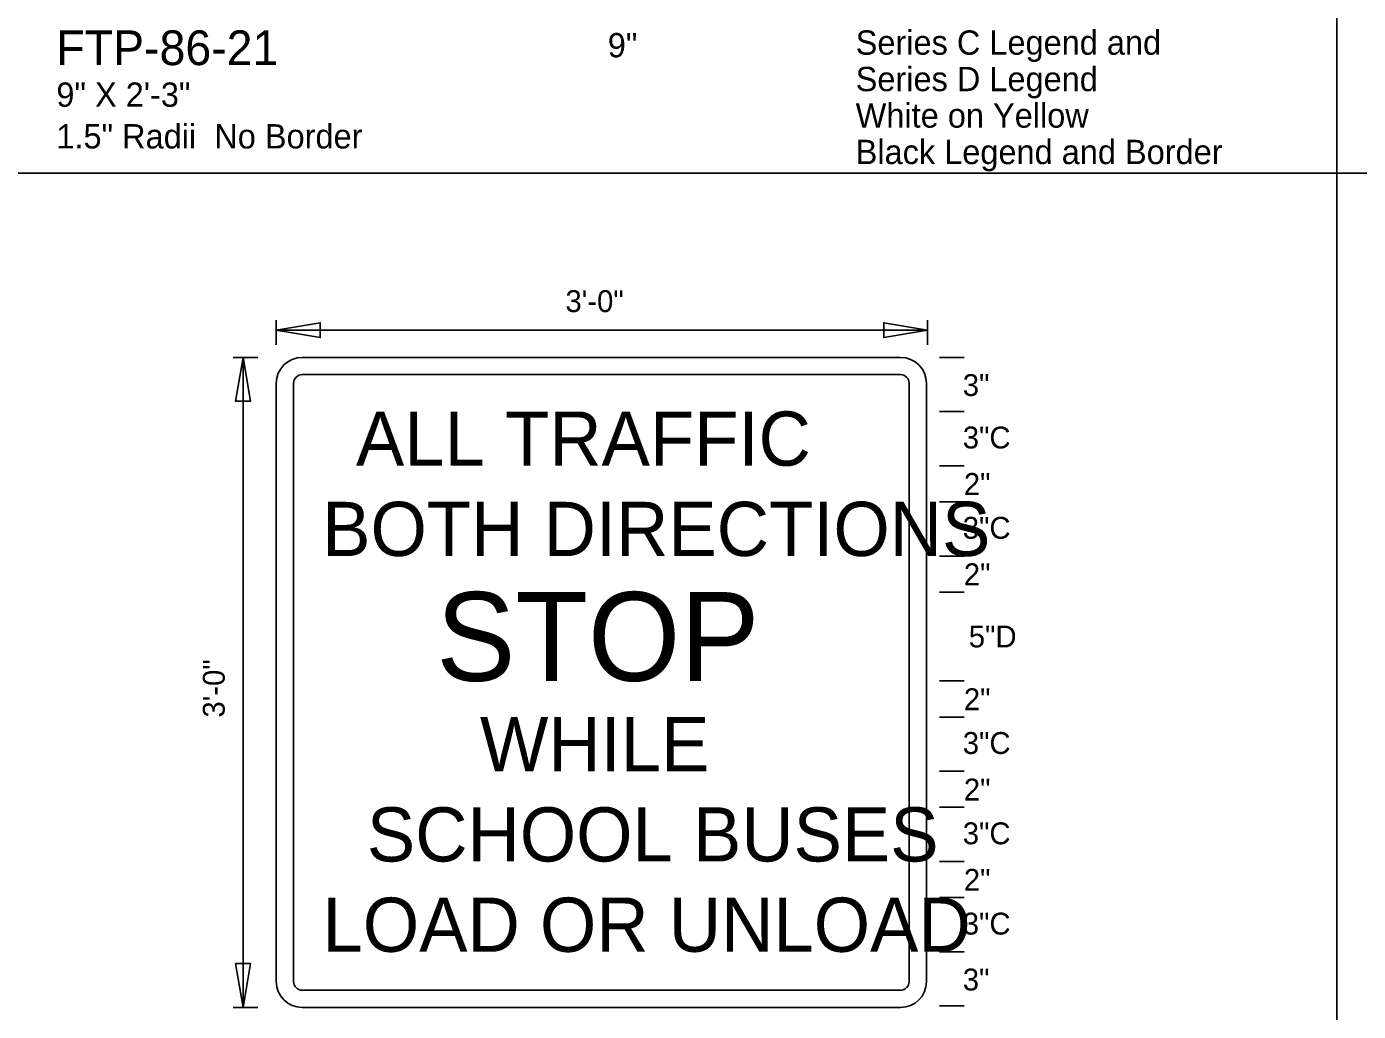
# Model space of a CAD drawing. Extents: x 0 to 770, y 0 to 495.
# Drawn here: x 196.4 to 388.1, y 209.3 to 351.1 of the extents above; entities that cross this region are included whole.
import ezdxf

# ---------------------------------------------------------------- set-up
doc = ezdxf.new("R2010")
doc.units = 0
for name, color, linetype in [('Default', 7, 'Continuous'), ('Dimension', 7, 'Continuous'), ('GSBWFill', 7, 'Continuous'), ('GSDims', 7, 'Continuous'), ('SheetLines_dp', 7, 'Continuous'), ('TextStructures', 7, 'Continuous')]:
    doc.layers.add(name, color=color, linetype=linetype)

msp = doc.modelspace()

# ---------------------------------------------------------------- linework, layer by layer
at = {"layer": 'Dimension'}
for points in [[(232.32, 307.4), (238.64, 306.33), (238.64, 308.47)], [(326.08, 307.4), (319.77, 308.47), (319.77, 306.33)], [(227.54, 303.48), (226.47, 297.17), (228.61, 297.17)], [(227.54, 209.89), (228.61, 216.2), (226.47, 216.2)]]:
    msp.add_lwpolyline(points, close=True, dxfattribs=at)
at = {"layer": 'GSBWFill'}
for p, q in [((322.18, 303.48), (236.06, 303.48)), ((232.32, 299.74), (232.32, 213.62)), ((234.82, 299.74), (234.82, 213.62)), ((322.18, 300.99), (236.06, 300.99)), ((323.43, 213.62), (323.43, 299.74)), ((325.92, 213.62), (325.92, 299.74)), ((236.06, 212.38), (322.18, 212.38)), ((236.06, 209.89), (322.18, 209.89))]:
    msp.add_line(p, q, dxfattribs=at)
for centre, radius, start, end in [((236.06, 299.74), 3.74, 90, 180), ((322.18, 299.74), 3.74, 0, 90), ((236.06, 299.74), 1.25, 90, 180), ((322.18, 299.74), 1.25, 0, 90), ((236.06, 213.62), 3.74, 180, 270), ((236.06, 213.62), 1.25, 180, 270), ((322.18, 213.62), 3.74, 270, 0), ((322.18, 213.62), 1.25, 270, 0)]:
    msp.add_arc(centre, radius, start, end, dxfattribs=at)
at = {"layer": 'GSDims'}
for p, q in [((232.32, 305.29), (232.32, 308.81)), ((326.08, 305.29), (326.08, 308.81)), ((232.32, 307.4), (326.08, 307.4)), ((229.65, 303.48), (226.13, 303.48)), ((227.54, 210.1), (227.54, 303.48)), ((327.82, 303.48), (331.34, 303.48)), ((327.82, 295.68), (331.34, 295.68)), ((327.82, 287.88), (331.34, 287.88)), ((327.82, 282.68), (331.34, 282.68)), ((327.82, 274.88), (331.34, 274.88)), ((327.82, 269.68), (331.34, 269.68)), ((327.82, 256.9), (331.34, 256.9)), ((327.82, 251.7), (331.34, 251.7)), ((327.82, 243.9), (331.34, 243.9)), ((327.82, 238.7), (331.34, 238.7)), ((327.82, 230.9), (331.34, 230.9)), ((327.82, 225.7), (331.34, 225.7)), ((327.82, 225.7), (331.34, 225.7)), ((327.82, 217.9), (331.34, 217.9)), ((229.65, 209.89), (226.13, 209.89)), ((327.82, 210.1), (331.34, 210.1))]:
    msp.add_line(p, q, dxfattribs=at)
at = {"layer": 'SheetLines_dp'}
for p, q in [((385, 0), (385, 495)), ((0, 330), (770, 330))]:
    msp.add_line(p, q, dxfattribs=at)

# ---------------------------------------------------------------- texts
at = {"layer": 'Default'}
for s, height, p in [('ALL TRAFFIC', 7.7998, (243.79, 287.88)), ('BOTH DIRECTIONS', 7.7998, (238.93, 274.88)), ('STOP', 12.785, (255.34, 256.9)), ('WHILE', 7.8, (261.64, 243.9)), ('SCHOOL BUSES', 7.7998, (245.36, 230.9)), ('LOAD OR UNLOAD', 7.7998, (238.98, 217.9))]:
    msp.add_text(s, height=height, dxfattribs=at).set_placement(p)
at = {"layer": 'TextStructures'}
for s, height, p in [('FTP-86-21', 5, (200.66, 345.55)), ('9"', 3.5, (280.04, 346.67)), ('Series C Legend and', 3.5, (315.73, 347.05)), ('Series D Legend', 3.5, (315.73, 341.8)), ('9" X 2\'-3"', 3.5, (200.66, 339.55)), ('White on Yellow', 3.5, (315.73, 336.55)), ('1.5" Radii  No Border   ', 3.5, (200.66, 333.55)), ('Black Legend and Border', 3.5, (315.73, 331.3)), ('3\'-0"', 3.15, (273.95, 310)), ('3"', 3.15, (331.15, 297.91)), ('3"C', 3.15, (331.15, 290.36)), ('2"', 3.15, (331.3, 283.67)), ('3"C', 3.15, (331.15, 277.36)), ('2"', 3.15, (331.3, 270.67)), ('5"D', 3.15, (332.01, 261.72)), ('2"', 3.15, (331.3, 252.68)), ('3"C', 3.15, (331.15, 246.38)), ('2"', 3.15, (331.3, 239.68)), ('3"C', 3.15, (331.15, 233.38)), ('2"', 3.15, (331.3, 226.68)), ('3"C', 3.15, (331.15, 220.38)), ('3"', 3.15, (331.15, 212.33))]:
    msp.add_text(s, height=height, dxfattribs=at).set_placement(p)
msp.add_text('3\'-0"', height=3.15, rotation=90, dxfattribs=at).set_placement((224.9, 251.62))

doc.saveas('drawing.dxf')
